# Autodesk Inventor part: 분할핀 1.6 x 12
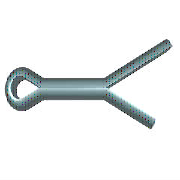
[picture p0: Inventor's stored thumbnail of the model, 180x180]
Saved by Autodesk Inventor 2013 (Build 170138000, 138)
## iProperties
IsCustomPart: 1
Created: 2012-02
Part Number: 분할핀 1.6 x 12
Material: 강철, 연강
Description: 분할 핀
Document SubType Name: Modeling
Standard: KS B 1321
Designer: mduedu
Standards Organization: KS
Language: ko-KR
Size Designation: 1.6 x  12
Categories: <MemberInstance><Categories><Category DisplayName="조임쇠" InternalName="e4da775c-781d-43d5-af7c-5136215cf5a6" Mnemonic="FSTN"><Category DisplayName="핀" InternalNa
Density: 1 g/cm^3
Author: mduedu
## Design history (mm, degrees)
sketch "스케치1"
  geometry: L1 (0, 0.7)-(7, 0.7); L2 (0, -0.7)-(7, -0.7); L3 (7, 0.7)-(12, 2.616); L4 (12, 2.616)-(12.234, 2.005); L5 (12.234, 2.005)-(7, 0); L6 (7, 0)-(14.734, -2.963); L7 (14.734, -2.963)-(14.5, -3.573); L8 (14.5, -3.573)-(7, -0.7); L9 (0, 0)-(-1.528, -0.645); L10 (0, 0)-(-1.528, 0.645); L11 (0, 0.7)-(0, -0.7); L12 (0, 0.7)-(-1.204, 1.267); L13 (0, -0.7)-(-1.204, -1.267); L14 (-3.2, 0)-(7, 0); L15 (7, 0.7)-(7, -0.7); A1 r 1.4 centre (-1.8, 0) between (-1.204, 1.267) and (-1.204, -1.267); A2 r 0.7 centre (-1.8, 0) between (-1.528, 0.645) and (-1.528, -0.645); 1 further point
  constraints: 30 end point, 5 point on circle, 4 parallel, 4 perpendicular, 4 point on line, 4 tangent, 2 centre point, 2 midpoint, 1 coincident, 1 horizontal
  dimensions: "d0" = 7 distance of L1.start L1.end (= MSIAB); "d1" = 12 horizontal distance of L1.start L3.end (= SNLG); "d2" = 159.037 deg angle of L1 L3; "d3" = 159.037 deg angle of L2 L8; "d4" = 2.5 horizontal distance of L3.end L7.end (= LGDIF); "d5" = 0.7 radius of A2 (= -0.5 x SNND1 + 0.5 x KBR); "d6" = 1.4 radius of A1 (= 0.5 x KBR); "d7" = 0.7 distance from line of L1 L9.start (= 0.5 x SNND1); "d8" = 0.7 distance between parallel lines of L2 L14 (= 0.5 x SNND1); "d9" = 1.8 distance from line of L11 A1.centre (= KOL - 0.5 x KBR)
extrude "본체" new body sketch "스케치1" stored distance "d10" = 1.4 (= SNND1); taper "d11" = 0 deg
workaxis "Work Axis1"
workplane "Work Plane1"
workplane "Work Plane3"
node "작업 평면3"
body "Solid1"
fillet "모깎기" dims "d12" = 0.49 (= 0.35 x SNND1)
other parameters: "SNND" = 1.6 [user parameter], "SNLG" = 12 [user parameter; used in 1 equation term], "SNND1" = 1.4 [user parameter; used in 5 equation terms], "KBR" = 2.8 [user parameter; used in 3 equation terms], "KOL" = 3.2 [user parameter; used in 1 equation term], "LGDIF" = 2.5 [user parameter; used in 1 equation term], "MSIAB" = 7 [user parameter; used in 1 equation term], "d15" = 0, "d16" = 0, "d17" = 0, "NNDMAX" = 7 [user parameter], "DSH" = 6 [user parameter], "NNDMIN" = 5.5 [user parameter], "d18" = 0
